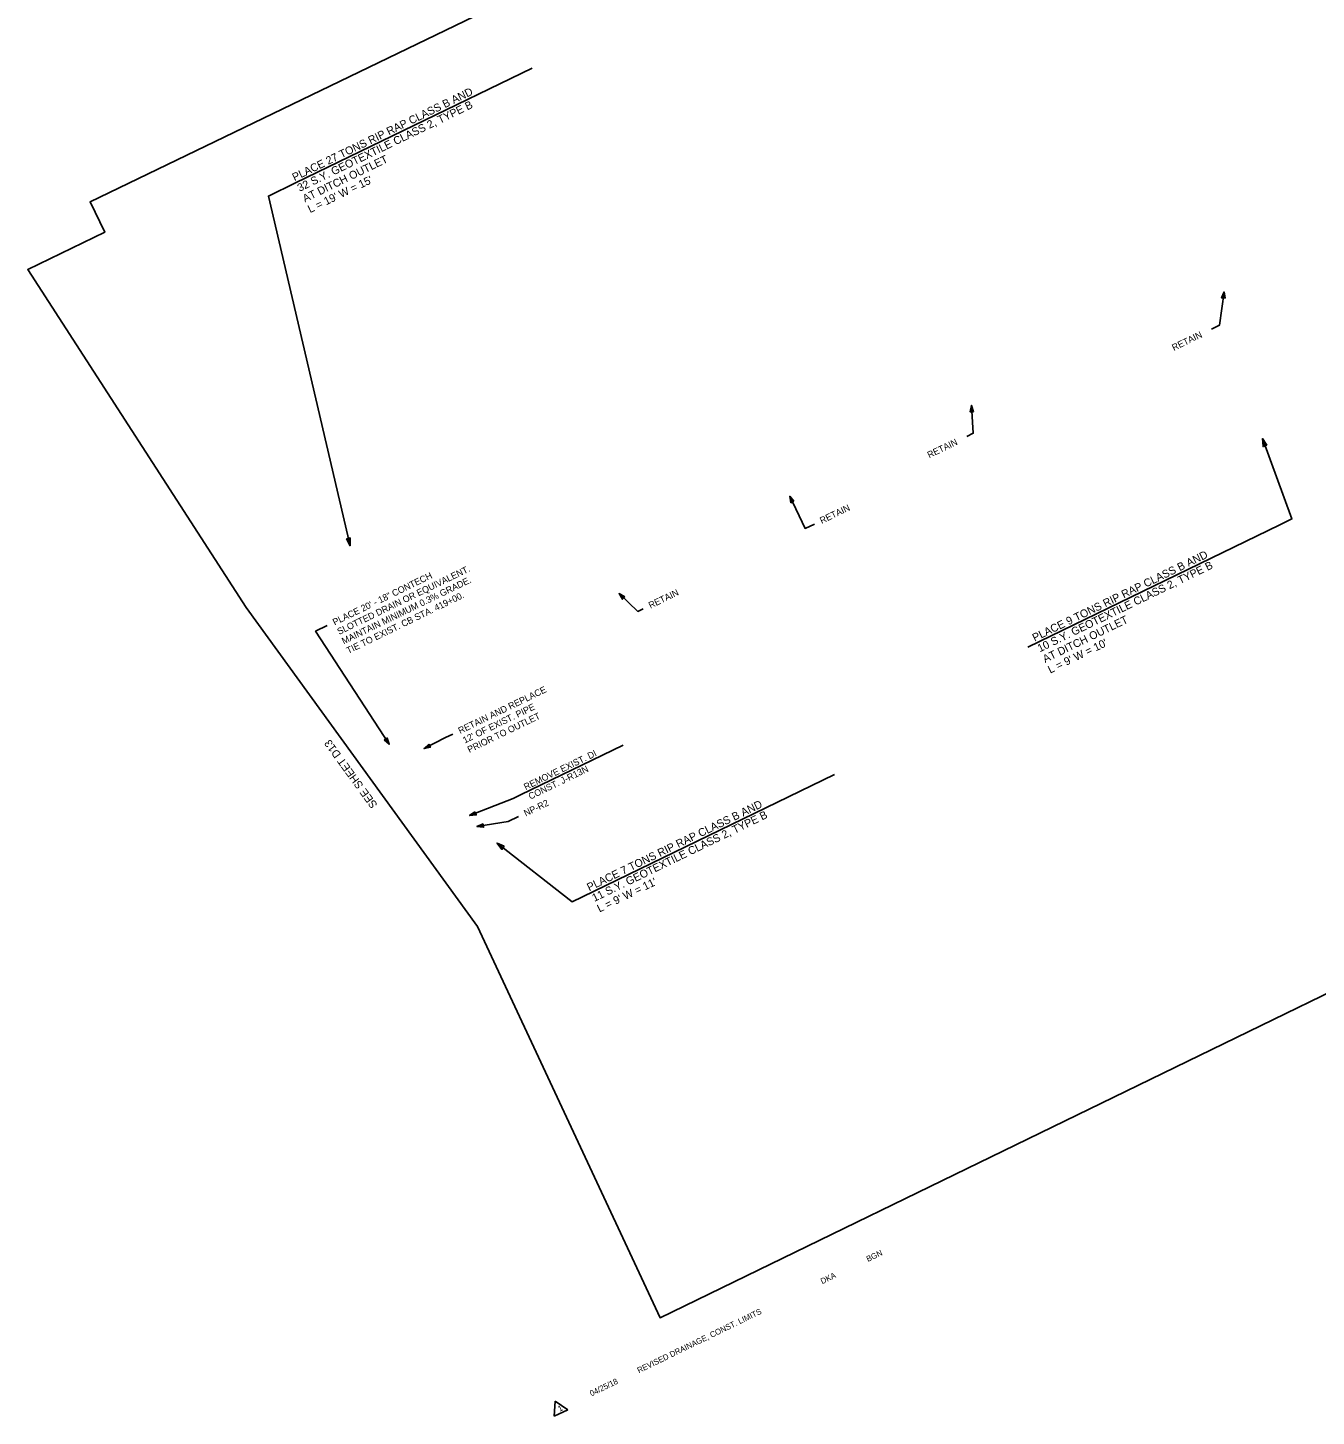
# Model space of a CAD drawing. Extents: x 1616914 to 1624709, y 1100483 to 1103157.
# Drawn here: x 1616914 to 1617894, y 1100483 to 1101540 of the extents above; entities that cross this region are included whole.
import ezdxf

# ---------------------------------------------------------------- set-up
doc = ezdxf.new("R2010")
doc.units = 0
for name, color, linetype in [('Level 2', 7, 'Continuous'), ('RD_EX_RW_TX', 7, 'Continuous'), ('RD_HC_Data_Tic', 7, 'Continuous'), ('RFP', 7, 'Continuous')]:
    doc.layers.add(name, color=color, linetype=linetype)

msp = doc.modelspace()

# ---------------------------------------------------------------- linework, layer by layer
at = {"layer": 'Level 2'}
for p, q in [((1617297.7, 1101509.7), (1617117.7, 1101422.2)), ((1617866.6, 1101162), (1617674.9, 1101068.8)), ((1617367, 1100994.3), (1617289, 1100956.4)), ((1617527.7, 1100972), (1617336, 1100878.8))]:
    msp.add_line(p, q, dxfattribs=at)
for points in [[(1617117.7, 1101422.2), (1617097.1, 1101412.2), (1617159.2, 1101146)], [(1617814.5, 1101311), (1617820.8, 1101314), (1617824.2, 1101339.3)], [(1617628.5, 1101229.3), (1617633.4, 1101231.7), (1617632, 1101252.9)], [(1617866.6, 1101162), (1617875.8, 1101166.5), (1617853.4, 1101227.6)], [(1617512.5, 1101162.6), (1617505.4, 1101159.2), (1617493.7, 1101183.7)], [(1617382.2, 1101098.1), (1617378.1, 1101096.1), (1617363.9, 1101109.6)], [(1617141.9, 1101085.3), (1617133, 1101081), (1617189, 1100994.9)], [(1617237.5, 1101002.7), (1617231.8, 1101000), (1617215.5, 1100991.6)], [(1617289, 1100956.4), (1617283.4, 1100953.7), (1617250.2, 1100940.6)], [(1617287.3, 1100940), (1617279.5, 1100936.2), (1617255.8, 1100932.3)], [(1617336, 1100878.8), (1617328.2, 1100875), (1617271.1, 1100919.7)]]:
    msp.add_lwpolyline(points, dxfattribs=at)
for points in [[(1617824.9, 1101334.4), (1617824.2, 1101339.3), (1617822.3, 1101334.7)], [(1617633.6, 1101248.1), (1617632, 1101252.9), (1617631, 1101248)], [(1617856.8, 1101222.7), (1617853.4, 1101227.6), (1617853.9, 1101221.6)], [(1617496.9, 1101179.9), (1617493.7, 1101183.7), (1617494.6, 1101178.8)], [(1617156.4, 1101151.2), (1617159.2, 1101146), (1617159.4, 1101152)], [(1617368.3, 1101107.2), (1617363.9, 1101109.6), (1617366.5, 1101105.3)], [(1617185.3, 1100998.2), (1617189, 1100994.9), (1617187.5, 1100999.6)], [(1617219.2, 1100995), (1617215.5, 1100991.6), (1617220.4, 1100992.7)], [(1617254.2, 1100943.6), (1617250.2, 1100940.6), (1617255.2, 1100941.1)], [(1617260.4, 1100934.4), (1617255.8, 1100932.3), (1617260.8, 1100931.8)], [(1617276.6, 1100917.3), (1617271.1, 1100919.7), (1617274.7, 1100914.9)]]:
    msp.add_lwpolyline(points, close=True, dxfattribs=at)
at = {"layer": 'RD_EX_RW_TX'}
for p, q in [((1617315.2, 1100495), (1617314.5, 1100483.4)), ((1617324.8, 1100488.4), (1617315.2, 1100495)), ((1617314.5, 1100483.4), (1617324.8, 1100488.4))]:
    msp.add_line(p, q, dxfattribs=at)
at = {"layer": 'RFP'}
msp.add_lwpolyline([(1617080.1, 1101099), (1617256.2, 1100856.1), (1617395.1, 1100558.4), (1618700.8, 1101193.7), (1618573.1, 1101494.1), (1618454.8, 1101769.8), (1618339.8, 1102037.7), (1618182.9, 1101960.1), (1618167.9, 1101990.6), (1616961.4, 1101407.9), (1616972.6, 1101384.7), (1616914, 1101356.4)], close=True, dxfattribs=at)
msp.add_lwpolyline([(1617080.1, 1101099), (1617256.2, 1100856.1), (1617395.1, 1100558.4), (1618700.8, 1101193.7), (1618573.1, 1101494.1), (1618454.8, 1101769.8), (1618339.8, 1102037.7), (1618182.9, 1101960.1), (1618167.9, 1101990.6), (1616961.4, 1101407.9), (1616972.6, 1101384.7), (1616914, 1101356.4)], close=True, dxfattribs=at)
msp.add_lwpolyline([(1617080.1, 1101099), (1617256.2, 1100856.1), (1617395.1, 1100558.4), (1618700.8, 1101193.7), (1618573.1, 1101494.1), (1618454.8, 1101769.8), (1618339.8, 1102037.7), (1618182.9, 1101960.1), (1618167.9, 1101990.6), (1616961.4, 1101407.9), (1616972.6, 1101384.7), (1616914, 1101356.4)], close=True, dxfattribs=at)
msp.add_lwpolyline([(1617080.1, 1101099), (1617256.2, 1100856.1), (1617395.1, 1100558.4), (1618700.8, 1101193.7), (1618573.1, 1101494.1), (1618454.8, 1101769.8), (1618339.8, 1102037.7), (1618182.9, 1101960.1), (1618167.9, 1101990.6), (1616961.4, 1101407.9), (1616972.6, 1101384.7), (1616914, 1101356.4)], close=True, dxfattribs=at)
msp.add_lwpolyline([(1617080.1, 1101099), (1617256.2, 1100856.1), (1617395.1, 1100558.4), (1618700.8, 1101193.7), (1618573.1, 1101494.1), (1618454.8, 1101769.8), (1618339.8, 1102037.7), (1618182.9, 1101960.1), (1618167.9, 1101990.6), (1616961.4, 1101407.9), (1616972.6, 1101384.7), (1616914, 1101356.4)], close=True, dxfattribs=at)

# ---------------------------------------------------------------- texts
at = {"layer": 'Level 2'}
for s, height, p in [('PLACE 27 TONS RIP RAP CLASS B AND', 6, (1617117, 1101423.5)), ('32 S.Y. GEOTEXTILE CLASS 2, TYPE B', 6, (1617120.9, 1101415.4)), ('AT DITCH OUTLET', 6, (1617124.9, 1101407.3)), ("L = 19' W = 15'", 6, (1617128.8, 1101399.2)), ('RETAIN', 5, (1617786, 1101294.3)), ('RETAIN', 5, (1617599.9, 1101212.6)), ('RETAIN', 5, (1617518.1, 1101162.6)), ('PLACE 9 TONS RIP RAP CLASS B AND', 6, (1617680.1, 1101073)), ('PLACE 20\' - 18" CONTECH', 5, (1617147.5, 1101085.3)), ('SLOTTED DRAIN OR EQUIVALENT.', 5, (1617150.9, 1101078.1)), ('10 S.Y. GEOTEXTILE CLASS 2, TYPE B', 6, (1617684, 1101064.9)), ('MAINTAIN MINIMUM 0.3% GRADE.', 5, (1617154.4, 1101070.9)), ('TIE TO EXIST. CB STA. 419+00.', 5, (1617157.9, 1101063.7)), ('RETAIN', 5, (1617387.8, 1101098.1)), ('AT DITCH OUTLET', 6, (1617688, 1101056.8)), ("L = 9' W = 10'", 6, (1617691.9, 1101048.7)), ('RETAIN AND REPLACE', 5, (1617243, 1101002.7)), ("12' OF EXIST. PIPE", 5, (1617246.5, 1100995.5)), ('PRIOR TO OUTLET', 5, (1617250, 1100988.3)), ('REMOVE EXIST. DI', 5, (1617292.9, 1100959.9)), ('CONST. J-R13N', 5, (1617296.4, 1100952.7)), ('NP-R2', 5, (1617292.9, 1100939.9)), ('PLACE 7 TONS RIP RAP CLASS B AND', 6, (1617341.2, 1100883)), ('11 S.Y. GEOTEXTILE CLASS 2, TYPE B', 6, (1617345.1, 1100874.9)), ("L = 9' W = 11'", 6, (1617349, 1100866.8))]:
    msp.add_text(s, height=height, rotation=25.9305, dxfattribs=at).set_placement(p)
at = {"layer": 'RD_EX_RW_TX'}
for s, p in [('BGN', (1617553.3, 1100600.8)), ('DKA', (1617518.5, 1100583.9)), ('REVISED DRAINAGE, CONST. LIMITS', (1617379, 1100516.1)), ('04/25/18', (1617342.9, 1100498.5)), ('1', (1617318.6, 1100486.8))]:
    msp.add_text(s, height=4.4, rotation=25.9321, dxfattribs=at).set_placement(p)
at = {"layer": 'RD_HC_Data_Tic'}
msp.add_text('SEE SHEET D13', height=6, rotation=125.9354, dxfattribs=at).set_placement((1617180.4, 1100948.9))

doc.saveas('drawing.dxf')
